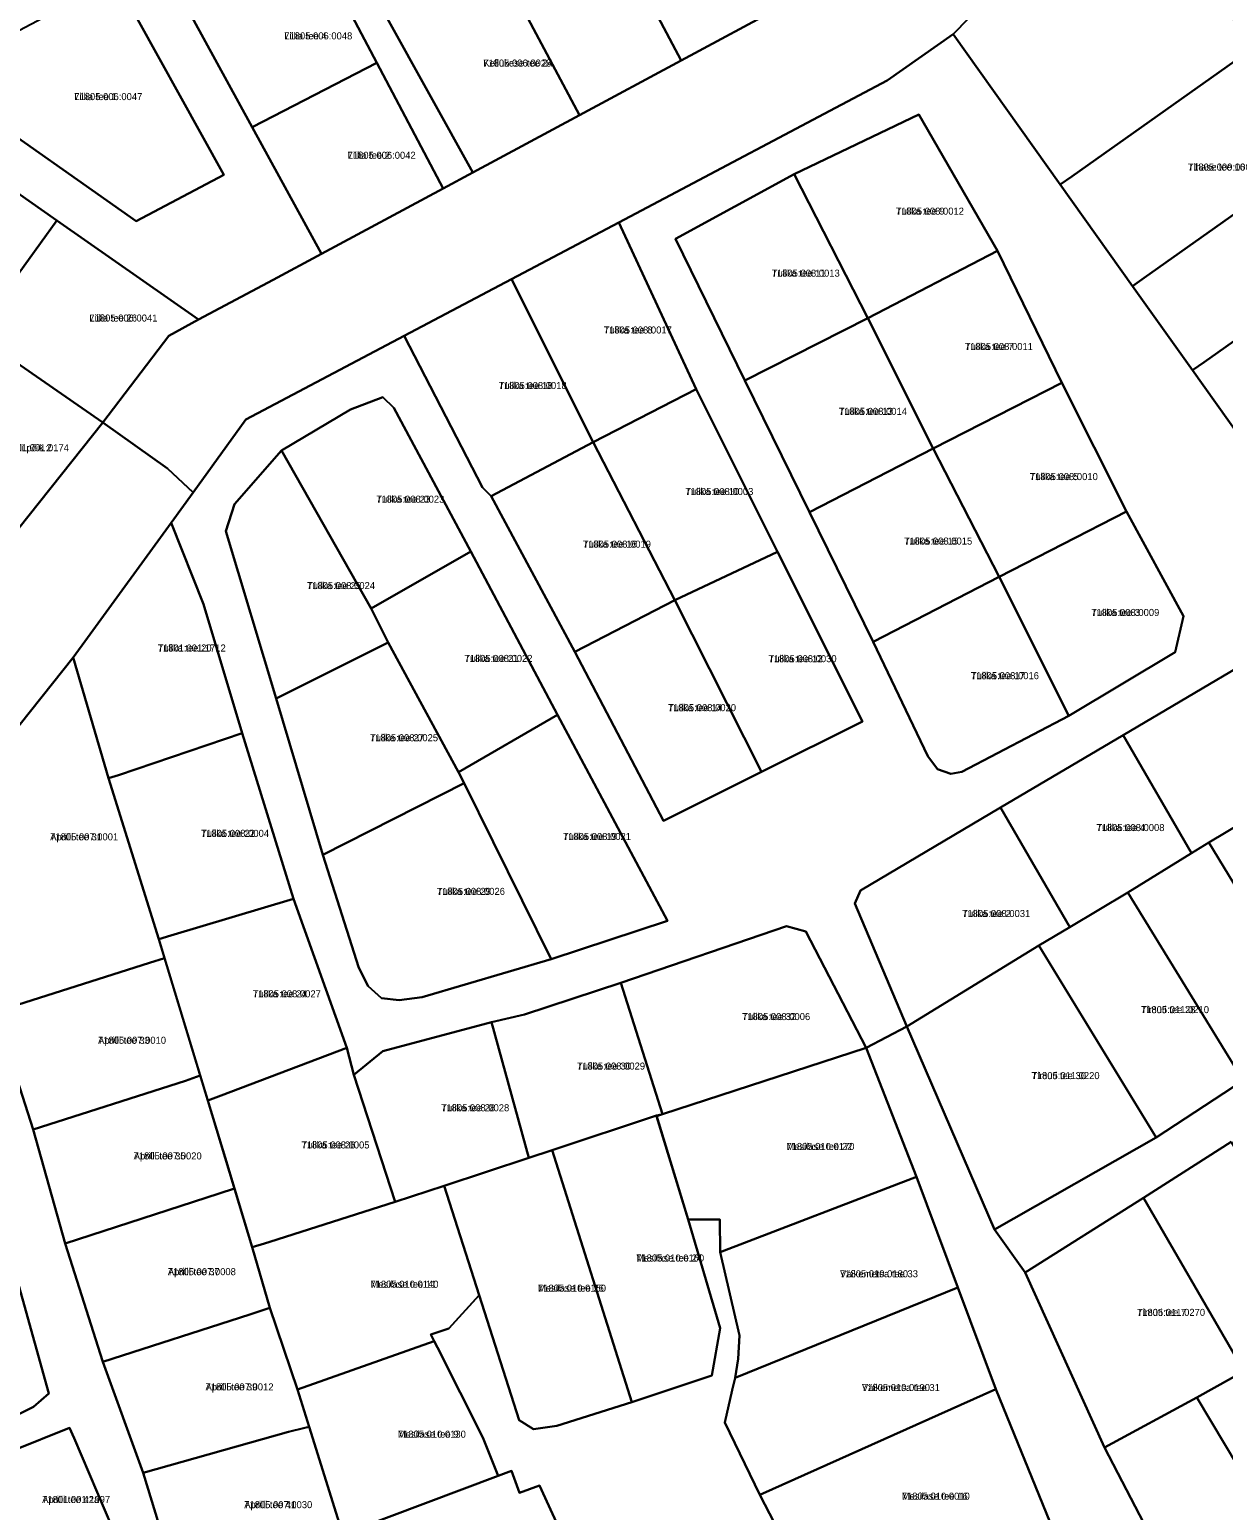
# Model space of a CAD drawing. Extents: x 529768 to 552006, y 6562269 to 6580975.
# Drawn here: x 537438.1 to 537692.6, y 6570909.2 to 6571224.9 of the extents above; entities that cross this region are included whole.
import ezdxf

# ---------------------------------------------------------------- set-up
doc = ezdxf.new("R2010")
doc.units = 0
for name, color, linetype in [('L_AADRESS', 7, 'Continuous'), ('PIIR', 7, 'Continuous'), ('TUNNUS', 7, 'Continuous')]:
    doc.layers.add(name, color=color, linetype=linetype)

msp = doc.modelspace()

# ---------------------------------------------------------------- linework, layer by layer
at = {"layer": 'PIIR'}
for points in [[(537500.31, 6571177.14), (537489.99, 6571171.59), (537474.12, 6571163.07), (537443.9, 6571184.21), (537419.45, 6571201.31), (537395.3, 6571218.2), (537377.23, 6571230.84), (537343.75, 6571217.76), (537339.6, 6571220.7), (537371.86, 6571234.8), (537396.97, 6571249.71), (537421.84, 6571264.48), (537442.4, 6571276.69), (537445.42, 6571282.22), (537449.08, 6571280.61), (537448.36, 6571271.95), (537460.05, 6571250.62), (537472.66, 6571227.61), (537485.53, 6571204.11)], [(537390.85, 6571233.33), (537424.42, 6571209.69), (537460.83, 6571184.07), (537479.5, 6571193.94), (537456.44, 6571235.68), (537440.86, 6571263.86), (537419.53, 6571251.4), (537390.92, 6571234.67)], [(537560.86, 6571248.83), (537582.81, 6571260.61), (537598.96, 6571230.13), (537577.01, 6571218.34)], [(537670.25, 6571260.12), (537672.36, 6571257.27), (537695.95, 6571225.42), (537696.81, 6571219.49), (537660.25, 6571193.6), (537657.8, 6571191.87), (537634.95, 6571223.95)], [(537539.13, 6571237.16), (537560.86, 6571248.83), (537577.01, 6571218.34), (537555.3, 6571206.68)], [(537512.12, 6571217.83), (537485.53, 6571204.11), (537472.66, 6571227.61), (537499.61, 6571241.55)], [(537537.66, 6571239.95), (537539.13, 6571237.16), (537555.3, 6571206.68), (537532.58, 6571194.47), (537514.31, 6571227.38)], [(537479.5, 6571193.94), (537460.83, 6571184.07), (537424.42, 6571209.69), (537434.62, 6571224.09), (537456.44, 6571235.68)], [(537526.24, 6571191.07), (537500.31, 6571177.14), (537485.53, 6571204.11), (537512.12, 6571217.83)], [(537673.22, 6571170.23), (537657.8, 6571191.87), (537660.25, 6571193.6), (537696.81, 6571219.49), (537712.16, 6571197.81), (537675.67, 6571171.96)], [(537601.09, 6571194.1), (537575.79, 6571180.3), (537590.57, 6571150.12), (537604.31, 6571122.04), (537617.9, 6571094.34), (537629.57, 6571069.98), (537631.63, 6571067.26), (537634.48, 6571066.24), (537636.82, 6571066.66), (537659.61, 6571078.6), (537682.26, 6571092.14), (537684.06, 6571099.88), (537671.93, 6571122.16), (537658.16, 6571149.62), (537644.43, 6571177.72), (537627.64, 6571206.78)], [(537601.09, 6571194.1), (537627.64, 6571206.78), (537644.43, 6571177.72), (537616.78, 6571163.36)], [(537443.9, 6571184.21), (537426.41, 6571160.03), (537409.79, 6571171.64), (537401.9, 6571177.15), (537419.45, 6571201.31)], [(537686, 6571152.27), (537673.22, 6571170.23), (537675.67, 6571171.96), (537712.16, 6571197.81), (537724.9, 6571179.82), (537688.45, 6571154)], [(537575.79, 6571180.3), (537601.09, 6571194.1), (537616.78, 6571163.36), (537590.57, 6571150.12)], [(537443.9, 6571184.21), (537474.12, 6571163.07), (537467.76, 6571159.65), (537453.72, 6571141.12), (537431.58, 6571156.41), (537426.41, 6571160.03)], [(537540.84, 6571171.74), (537563.68, 6571183.8), (537580.16, 6571148.22), (537558.21, 6571136.94)], [(537698.8, 6571134.31), (537686, 6571152.27), (537688.45, 6571154), (537724.9, 6571179.82), (537737.98, 6571161.35), (537701.27, 6571136.01)], [(537616.78, 6571163.36), (537644.43, 6571177.72), (537658.16, 6571149.62), (537630.67, 6571135.62)], [(537534.65, 6571127.3), (537517.95, 6571159.64), (537540.84, 6571171.74), (537558.21, 6571136.94), (537536.46, 6571125.42)], [(537590.57, 6571150.12), (537616.78, 6571163.36), (537630.67, 6571135.62), (537604.31, 6571122.04)], [(537453.72, 6571141.12), (537431.35, 6571113.1), (537410.24, 6571128.44), (537431.58, 6571156.41)], [(537558.21, 6571136.94), (537580.16, 6571148.22), (537597.52, 6571113.54), (537575.63, 6571103.26)], [(537630.67, 6571135.62), (537658.16, 6571149.62), (537671.93, 6571122.16), (537644.75, 6571108.24)], [(537500.59, 6571048.96), (537508.3, 6571024.88), (537510.26, 6571020.92), (537513.09, 6571018.38), (537516.87, 6571017.96), (537521.76, 6571018.6), (537549.24, 6571026.74), (537574.05, 6571034.88), (537550.64, 6571078.82), (537532.17, 6571113.62), (537515.76, 6571144.28), (537513.42, 6571146.52), (537506.49, 6571143.94), (537491.82, 6571135.18), (537481.77, 6571123.7), (537479.91, 6571118), (537490.62, 6571082.3)], [(537506.49, 6571143.94), (537513.42, 6571146.52), (537515.76, 6571144.28), (537532.17, 6571113.62), (537510.94, 6571101.48), (537491.82, 6571135.18)], [(537536.46, 6571125.42), (537558.21, 6571136.94), (537575.63, 6571103.26), (537554.29, 6571092.22)], [(537604.31, 6571122.04), (537630.67, 6571135.62), (537644.75, 6571108.24), (537617.9, 6571094.34)], [(537479.91, 6571118), (537481.77, 6571123.7), (537491.82, 6571135.18), (537510.94, 6571101.48), (537514.55, 6571094.24), (537490.62, 6571082.3)], [(537450.46, 6571095.2), (537468.27, 6571119.75), (537475.14, 6571102.43), (537483.42, 6571074.87), (537457.03, 6571065.98), (537454.93, 6571065.27), (537447.4, 6571091.06)], [(537644.75, 6571108.24), (537671.93, 6571122.16), (537684.06, 6571099.88), (537682.26, 6571092.14), (537659.61, 6571078.6)], [(537514.55, 6571094.24), (537510.94, 6571101.48), (537532.17, 6571113.62), (537550.64, 6571078.82), (537529.53, 6571066.62)], [(537575.63, 6571103.26), (537597.52, 6571113.54), (537615.62, 6571077.36), (537594.08, 6571066.64)], [(537634.48, 6571066.24), (537631.63, 6571067.26), (537629.57, 6571069.98), (537617.9, 6571094.34), (537644.75, 6571108.24), (537659.61, 6571078.6), (537636.82, 6571066.66)], [(537575.63, 6571103.26), (537594.08, 6571066.64), (537573.23, 6571056.18), (537554.29, 6571092.22)], [(537490.62, 6571082.3), (537514.55, 6571094.24), (537529.53, 6571066.62), (537530.7, 6571064.24), (537500.59, 6571048.96)], [(537418.1, 6571054.26), (537447.4, 6571091.06), (537454.93, 6571065.27), (537465.64, 6571030.96), (537466.86, 6571026.92), (537463.68, 6571025.91), (537430.75, 6571015.51)], [(537685.78, 6571049.28), (537671.22, 6571074.48), (537698.65, 6571090.71), (537713.88, 6571066.16), (537689.49, 6571051.56)], [(537530.7, 6571064.24), (537529.53, 6571066.62), (537550.64, 6571078.82), (537574.05, 6571034.88), (537549.24, 6571026.74)], [(537734.79, 6571078.68), (537737.32, 6571080.23), (537740.35, 6571076.02), (537737.74, 6571073.68), (537733.46, 6571069.84), (537732.28, 6571065.71), (537718.96, 6571019.26), (537717.6, 6571014.12), (537713.81, 6571011.49), (537689.49, 6571051.56), (537713.88, 6571066.16)], [(537465.64, 6571030.96), (537454.93, 6571065.27), (537457.03, 6571065.98), (537483.42, 6571074.87), (537494.35, 6571039.56), (537468.22, 6571031.74)], [(537645.07, 6571059.04), (537671.22, 6571074.48), (537685.78, 6571049.28), (537672.19, 6571040.93), (537659.81, 6571033.55)], [(537516.87, 6571017.96), (537513.09, 6571018.38), (537510.26, 6571020.92), (537508.3, 6571024.88), (537500.59, 6571048.96), (537530.7, 6571064.24), (537549.24, 6571026.74), (537521.76, 6571018.6)], [(537614.03, 6571038.56), (537615.24, 6571041.38), (537645.07, 6571059.04), (537659.81, 6571033.55), (537653.22, 6571029.63), (537625.11, 6571012.36)], [(537689.49, 6571051.56), (537713.81, 6571011.49), (537696.77, 6571000.83), (537672.19, 6571040.93), (537685.78, 6571049.28)], [(537672.19, 6571040.93), (537696.77, 6571000.83), (537678.26, 6570988.72), (537653.22, 6571029.63), (537659.81, 6571033.55)], [(537476.09, 6570996.58), (537465.64, 6571030.96), (537468.22, 6571031.74), (537494.35, 6571039.56), (537505.73, 6571007.78), (537478.92, 6570997.64)], [(537564.09, 6571021.66), (537599.44, 6571033.76), (537603.59, 6571032.6), (537616.42, 6571007.8), (537573.02, 6570993.68)], [(537625.11, 6571012.36), (537653.22, 6571029.63), (537678.26, 6570988.72), (537643.79, 6570969.07)], [(537430.75, 6571015.51), (537463.68, 6571025.91), (537466.86, 6571026.92), (537474.44, 6571001.94), (537471.33, 6571000.77), (537438.88, 6570990.41)], [(537536.55, 6571013.3), (537543.59, 6571014.88), (537564.09, 6571021.66), (537573.02, 6570993.68), (537571.72, 6570993.36), (537549.5, 6570986.02), (537544.49, 6570984.35)], [(537507.19, 6571002.08), (537513.38, 6571007.06), (537536.55, 6571013.3), (537544.49, 6570984.35), (537526.48, 6570978.36), (537516, 6570974.94)], [(537485.56, 6570965.3), (537476.09, 6570996.58), (537478.92, 6570997.64), (537505.73, 6571007.78), (537507.19, 6571002.08), (537516, 6570974.94), (537489.32, 6570966.44), (537488.2, 6570966.1)], [(537585.22, 6570971.22), (537578.45, 6570971.23), (537571.75, 6570993.27), (537573.02, 6570993.68), (537616.42, 6571007.8), (537627.12, 6570980.3), (537585.32, 6570964.25)], [(537438.88, 6570990.41), (537471.33, 6571000.77), (537474.44, 6571001.94), (537480.25, 6570982.79), (537481.76, 6570977.81), (537478.48, 6570976.74), (537445.7, 6570966.07)], [(537571.72, 6570993.36), (537578.45, 6570971.23), (537585.28, 6570948.05), (537583.53, 6570937.97), (537566.45, 6570932.23), (537549.5, 6570986.02)], [(537433.61, 6570965.01), (537423.88, 6570990.29), (537408.09, 6570984.15), (537389.42, 6570970.36), (537396.98, 6570950.75), (537418.21, 6570932.21), (537422.36, 6570929.64), (537426.56, 6570929.24), (537435.5, 6570929.56), (537438.95, 6570931.25), (537442.2, 6570934.07)], [(537694.21, 6570987.76), (537715.54, 6570950.85), (537713.84, 6570947.89), (537698.01, 6570939.4), (537695.19, 6570941.87), (537675.53, 6570975.82)], [(537542.44, 6570928.39), (537533.93, 6570955.07), (537526.48, 6570978.36), (537544.49, 6570984.35), (537549.5, 6570986.02), (537566.45, 6570932.23), (537550.48, 6570927.21), (537545.49, 6570926.47)], [(537445.7, 6570966.07), (537478.48, 6570976.74), (537481.76, 6570977.81), (537485.56, 6570965.3), (537489.33, 6570952.36), (537485.06, 6570950.97), (537453.68, 6570940.86)], [(537485.56, 6570965.3), (537488.2, 6570966.1), (537489.32, 6570966.44), (537516, 6570974.94), (537526.48, 6570978.36), (537533.93, 6570955.07), (537527.46, 6570947.99), (537523.63, 6570946.65), (537524.33, 6570945.26), (537495.23, 6570934.95), (537489.33, 6570952.36)], [(537589.16, 6570941.48), (537589.4, 6570946.5), (537585.32, 6570964.25), (537627.12, 6570980.3), (537635.95, 6570956.72), (537588.47, 6570937.45)], [(537667.24, 6570922.6), (537650.31, 6570959.87), (537675.53, 6570975.82), (537695.19, 6570941.87), (537698.01, 6570939.4), (537686.9, 6570933.26)], [(537433.61, 6570965.01), (537442.2, 6570934.07), (537438.95, 6570931.25), (537435.5, 6570929.56), (537426.56, 6570929.24), (537422.36, 6570929.64), (537418.21, 6570932.21), (537396.98, 6570950.75)], [(537586.32, 6570927.93), (537587.83, 6570934.82), (537588.47, 6570937.45), (537635.95, 6570956.72), (537644.08, 6570934.99), (537593.78, 6570912.53)], [(537453.68, 6570940.86), (537485.06, 6570950.97), (537489.33, 6570952.36), (537495.23, 6570934.95), (537497.7, 6570927), (537496.79, 6570926.76), (537493.3, 6570925.94), (537462.29, 6570917.16)], [(537710.25, 6570894.06), (537686.9, 6570933.26), (537698.01, 6570939.4), (537713.84, 6570947.89), (537715.54, 6570950.85), (537721.33, 6570942.88), (537739.54, 6570911.7)], [(537504.84, 6570904.07), (537497.7, 6570927), (537495.23, 6570934.95), (537524.33, 6570945.26), (537525.03, 6570943.88), (537534.72, 6570924.75), (537537.98, 6570916.56), (537506.99, 6570904.88)], [(537605.23, 6570890.42), (537593.78, 6570912.53), (537644.08, 6570934.99), (537655.66, 6570906.61), (537613.25, 6570887.92)], [(537688.78, 6570881.15), (537667.24, 6570922.6), (537686.9, 6570933.26), (537710.25, 6570894.06)], [(537447.95, 6570894.76), (537425.45, 6570912.88), (537434.62, 6570921.92), (537446.57, 6570926.76), (537447.57, 6570924.58), (537455.75, 6570905.4)], [(537462.29, 6570917.16), (537493.3, 6570925.94), (537496.79, 6570926.76), (537497.7, 6570927), (537504.84, 6570904.07), (537505.11, 6570903.21), (537503.78, 6570902.75), (537501.45, 6570901.96), (537469.9, 6570892.3)], [(537523.36, 6570843.75), (537520.56, 6570853), (537513.69, 6570875.65), (537513.05, 6570877.71), (537505.11, 6570903.21), (537504.84, 6570904.07), (537506.99, 6570904.88), (537537.98, 6570916.56), (537540.79, 6570917.62), (537542.56, 6570912.94), (537546.77, 6570914.52), (537557.06, 6570892.01), (537549.15, 6570889.02), (537559.7, 6570856.71), (537526.52, 6570844.88)]]:
    msp.add_lwpolyline(points, close=True, dxfattribs=at)
for points in [[(537670.25, 6571260.12), (537634.95, 6571223.95), (537620.91, 6571214.06), (537563.68, 6571183.8), (537540.84, 6571171.74), (537517.95, 6571159.64), (537484.17, 6571141.76), (537472.94, 6571126.25), (537467.51, 6571131.36), (537453.72, 6571141.12), (537467.76, 6571159.65), (537474.12, 6571163.07), (537489.99, 6571171.59), (537500.31, 6571177.14), (537526.24, 6571191.07), (537532.58, 6571194.47), (537555.3, 6571206.68), (537577.01, 6571218.34), (537598.96, 6571230.13)], [(537514.31, 6571227.38), (537532.58, 6571194.47), (537526.24, 6571191.07), (537512.12, 6571217.83), (537499.61, 6571241.55)], [(537698.65, 6571090.71), (537671.22, 6571074.48), (537645.07, 6571059.04), (537615.24, 6571041.38), (537614.03, 6571038.56), (537625.11, 6571012.36), (537616.42, 6571007.8), (537603.59, 6571032.6), (537599.44, 6571033.76), (537564.09, 6571021.66), (537543.59, 6571014.88), (537536.55, 6571013.3), (537513.38, 6571007.06), (537507.19, 6571002.08), (537505.73, 6571007.78), (537494.35, 6571039.56), (537483.42, 6571074.87), (537475.14, 6571102.43), (537468.27, 6571119.75), (537472.94, 6571126.25), (537484.17, 6571141.76), (537517.95, 6571159.64), (537534.65, 6571127.3), (537536.46, 6571125.42), (537554.29, 6571092.22), (537573.23, 6571056.18), (537594.08, 6571066.64), (537615.62, 6571077.36), (537597.52, 6571113.54), (537580.16, 6571148.22), (537563.68, 6571183.8), (537620.91, 6571214.06), (537634.95, 6571223.95), (537657.8, 6571191.87), (537673.22, 6571170.23), (537686, 6571152.27), (537698.8, 6571134.31)], [(537431.35, 6571113.1), (537453.72, 6571141.12), (537467.51, 6571131.36), (537472.94, 6571126.25), (537468.27, 6571119.75), (537450.46, 6571095.2), (537447.4, 6571091.06), (537418.1, 6571054.26)], [(537430.75, 6571015.51), (537438.88, 6570990.41), (537445.7, 6570966.07), (537453.68, 6570940.86), (537462.29, 6570917.16), (537469.9, 6570892.3)], [(537655.66, 6570906.61), (537644.08, 6570934.99), (537635.95, 6570956.72), (537627.12, 6570980.3), (537616.42, 6571007.8), (537625.11, 6571012.36), (537643.79, 6570969.07), (537650.31, 6570959.87), (537667.24, 6570922.6), (537688.78, 6570881.15)], [(537694.21, 6570987.76), (537675.53, 6570975.82), (537650.31, 6570959.87), (537643.79, 6570969.07), (537678.26, 6570988.72), (537696.77, 6571000.83)], [(537557.06, 6570892.01), (537546.77, 6570914.52), (537542.56, 6570912.94), (537540.79, 6570917.62), (537537.98, 6570916.56), (537534.72, 6570924.75), (537525.03, 6570943.88), (537524.33, 6570945.26), (537523.63, 6570946.65), (537527.46, 6570947.99), (537533.93, 6570955.07), (537542.44, 6570928.39), (537545.49, 6570926.47), (537550.48, 6570927.21), (537566.45, 6570932.23), (537583.53, 6570937.97), (537585.28, 6570948.05), (537578.45, 6570971.23), (537585.22, 6570971.22), (537585.32, 6570964.25), (537589.4, 6570946.5), (537589.16, 6570941.48), (537588.47, 6570937.45), (537587.83, 6570934.82), (537586.32, 6570927.93), (537593.78, 6570912.53), (537605.23, 6570890.42)], [(537455.75, 6570905.4), (537447.57, 6570924.58), (537446.57, 6570926.76), (537434.62, 6570921.92)]]:
    msp.add_lwpolyline(points, dxfattribs=at)

# ---------------------------------------------------------------- texts
at = {"layer": 'L_AADRESS'}
for s, p in [('Liilia tee 4', (537492.38, 6571222.83)), ('Kellukese tee 24', (537534.8, 6571217.04)), ('Liilia tee 1', (537447.62, 6571209.88)), ('Liilia tee 2', (537505.89, 6571197.37)), ('Tihase tee 16', (537685.01, 6571194.86)), ('Tulika tee 9', (537622.76, 6571185.46)), ('Tulika tee 11', (537596.29, 6571172.24)), ('Liilia tee 26', (537450.84, 6571162.67)), ('Tulika tee 8', (537560.5, 6571160.12)), ('Tulika tee 7', (537637.47, 6571156.59)), ('Tulika tee 18', (537538.08, 6571148.28)), ('Tulika tee 13', (537610.62, 6571142.77)), ('Aprilli põik 2', (537431.98, 6571135.01)), ('Tulika tee 5', (537651.3, 6571128.86)), ('Tulika tee 10', (537577.87, 6571125.68)), ('Tulika tee 23', (537512, 6571124.04)), ('Tulika tee 15', (537624.53, 6571115.11)), ('Tulika tee 16', (537556.05, 6571114.46)), ('Tulika tee 25', (537497.23, 6571105.62)), ('Tulika tee 3', (537664.41, 6571099.89)), ('Tulika tee 20', (537465.41, 6571092.31)), ('Tulika tee 21', (537530.79, 6571090.09)), ('Tulika tee 12', (537595.62, 6571090.03)), ('Tulika tee 17', (537638.75, 6571086.41)), ('Tulika tee 14', (537574.18, 6571079.59)), ('Tulika tee 27', (537510.66, 6571073.18)), ('Aprilli tee 31', (537442.48, 6571052.05)), ('Tulika tee 22', (537474.64, 6571052.79)), ('Tulika tee 19', (537551.79, 6571052.12)), ('Tulika tee 4', (537665.51, 6571054.02)), ('Tulika tee 29', (537524.92, 6571040.42)), ('Tulika tee 2', (537636.9, 6571035.7)), ('Tulika tee 24', (537485.68, 6571018.58)), ('Timuti tee 28', (537675, 6571015.2)), ('Tulika tee 32', (537589.99, 6571013.72)), ('Aprilli tee 33', (537452.68, 6571008.67)), ('Tulika tee 30', (537554.79, 6571003.17)), ('Timuti tee 30', (537651.68, 6571001.13)), ('Tulika tee 28', (537525.84, 6570994.28)), ('Tulika tee 26', (537496.05, 6570986.35)), ('Mesilase tee 22', (537599.42, 6570986.03)), ('Aprilli tee 35', (537460.28, 6570984.01)), ('Mesilase tee 24', (537567.39, 6570962.24)), ('Aprilli tee 37', (537467.56, 6570959.33)), ('Väikemetsa tee 33', (537610.85, 6570958.88)), ('Mesilase tee 11', (537510.75, 6570956.65)), ('Mesilase tee 26', (537546.46, 6570955.81)), ('Timuti tee 7', (537674.16, 6570950.65)), ('Aprilli tee 39', (537475.59, 6570934.76)), ('Väikemetsa tee 31', (537615.52, 6570934.62)), ('Mesilase tee 9', (537516.59, 6570924.67)), ('Aprilli tee 42a', (537440.77, 6570910.76)), ('Mesilase tee 16', (537624.01, 6570911.46)), ('Aprilli tee 41', (537483.85, 6570909.65))]:
    msp.add_text(s, height=1.5, dxfattribs=at).set_placement(p)
at = {"layer": 'TUNNUS'}
for s, p in [('71805:006:0048', (537492.38, 6571222.83)), ('71805:006:0028', (537534.8, 6571217.04)), ('71805:006:0047', (537447.62, 6571209.88)), ('71805:006:0042', (537505.89, 6571197.37)), ('71805:009:0001', (537685.01, 6571194.86)), ('71805:008:0012', (537622.76, 6571185.46)), ('71805:008:0013', (537596.29, 6571172.24)), ('71805:006:0041', (537450.84, 6571162.67)), ('71805:008:0017', (537560.5, 6571160.12)), ('71805:008:0011', (537637.47, 6571156.59)), ('71805:008:0018', (537538.08, 6571148.28)), ('71805:008:0014', (537610.62, 6571142.77)), ('71901:001:0174', (537431.98, 6571135.01)), ('71805:008:0010', (537651.3, 6571128.86)), ('71805:008:0003', (537577.87, 6571125.68)), ('71805:008:0023', (537512, 6571124.04)), ('71805:008:0015', (537624.53, 6571115.11)), ('71805:008:0019', (537556.05, 6571114.46)), ('71805:008:0024', (537497.23, 6571105.62)), ('71805:008:0009', (537664.41, 6571099.89)), ('71801:001:1712', (537465.41, 6571092.31)), ('71805:008:0022', (537530.79, 6571090.09)), ('71805:008:0030', (537595.62, 6571090.03)), ('71805:008:0016', (537638.75, 6571086.41)), ('71805:008:0020', (537574.18, 6571079.59)), ('71805:008:0025', (537510.66, 6571073.18)), ('71805:007:0001', (537442.48, 6571052.05)), ('71805:008:0004', (537474.64, 6571052.79)), ('71805:008:0021', (537551.79, 6571052.12)), ('71805:008:0008', (537665.51, 6571054.02)), ('71805:008:0026', (537524.92, 6571040.42)), ('71805:008:0031', (537636.9, 6571035.7)), ('71805:008:0027', (537485.68, 6571018.58)), ('71805:011:0210', (537675, 6571015.2)), ('71805:008:0006', (537589.99, 6571013.72)), ('71805:007:0010', (537452.68, 6571008.67)), ('71805:008:0029', (537554.79, 6571003.17)), ('71805:011:0220', (537651.68, 6571001.13)), ('71805:008:0028', (537525.84, 6570994.28)), ('71805:008:0005', (537496.05, 6570986.35)), ('71805:010:0170', (537599.42, 6570986.03)), ('71805:007:0020', (537460.28, 6570984.01)), ('71805:010:0160', (537567.39, 6570962.24)), ('71805:007:0008', (537467.56, 6570959.33)), ('71805:010:0180', (537610.85, 6570958.88)), ('71805:010:0140', (537510.75, 6570956.65)), ('71805:010:0150', (537546.46, 6570955.81)), ('71805:011:0270', (537674.16, 6570950.65)), ('71805:007:0012', (537475.59, 6570934.76)), ('71805:010:0190', (537615.52, 6570934.62)), ('71805:010:0130', (537516.59, 6570924.67)), ('71801:001:1997', (537440.77, 6570910.76)), ('71805:010:0010', (537624.01, 6570911.46)), ('71805:007:0030', (537483.85, 6570909.65))]:
    msp.add_text(s, height=1.5, dxfattribs=at).set_placement(p)

doc.saveas('drawing.dxf')
